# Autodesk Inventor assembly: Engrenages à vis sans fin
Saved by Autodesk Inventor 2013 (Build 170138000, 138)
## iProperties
Created: 2011-07
Part Number: Engrenages à vis sans fin
Document SubType Name: Assembly
Designer: Laur
ClientObjectVersion: 1
Author: Laur
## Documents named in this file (2)
- D:\_an13-14\FORMULAIRE_2014\Sujet E4 Poissy-ParisXIXe_janv2012\Modélisation_7970_shimano\vis sans fin arbrée\Design Accelerator\Engrenages à vis sans fin1.iam
- D:\_an13-14\FORMULAIRE_2014\Sujet E4 Poissy-ParisXIXe_janv2012\Modélisation_7970_shimano\vis sans fin arbrée\Design Accelerator\Vis sans fin2.ipt
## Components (1 placed, 1 different names)
1. Vis sans fin:1
